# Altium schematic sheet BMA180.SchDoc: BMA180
size Letter
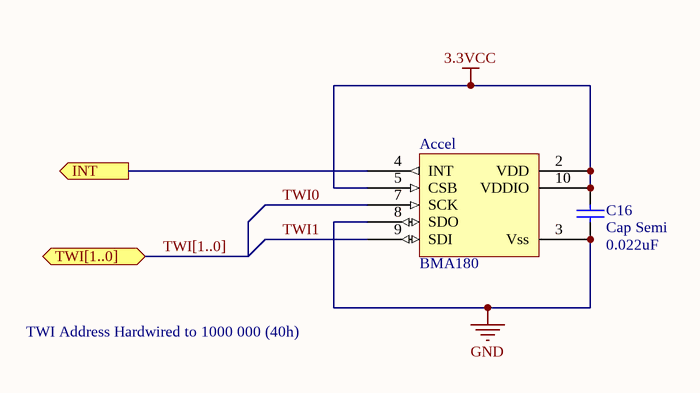
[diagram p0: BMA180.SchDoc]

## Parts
Accel  BMA180  [BMA180 - ECESHOP]
C16  Cap Semi  value 0.022uF  [CAPC2012N]

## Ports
INT (out), TWI[1..0] (bidir)

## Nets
3.3VCC: Accel.2(VDD) Accel.5(CSB) Accel.10(VDDIO) C16.2
GND: Accel.3(Vss) Accel.8(SDO) C16.1
INT: Accel.4(INT) ; port INT
TWI0: Accel.7(SCK)
TWI1: Accel.9(SDI)

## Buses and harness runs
bus TWI[1..0] = port TWI[1..0]

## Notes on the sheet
- TWI Address Hardwired to 1000 000 (40h)

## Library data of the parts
C16 = Cap Semi: Capacitor (Semiconductor SIM Model)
